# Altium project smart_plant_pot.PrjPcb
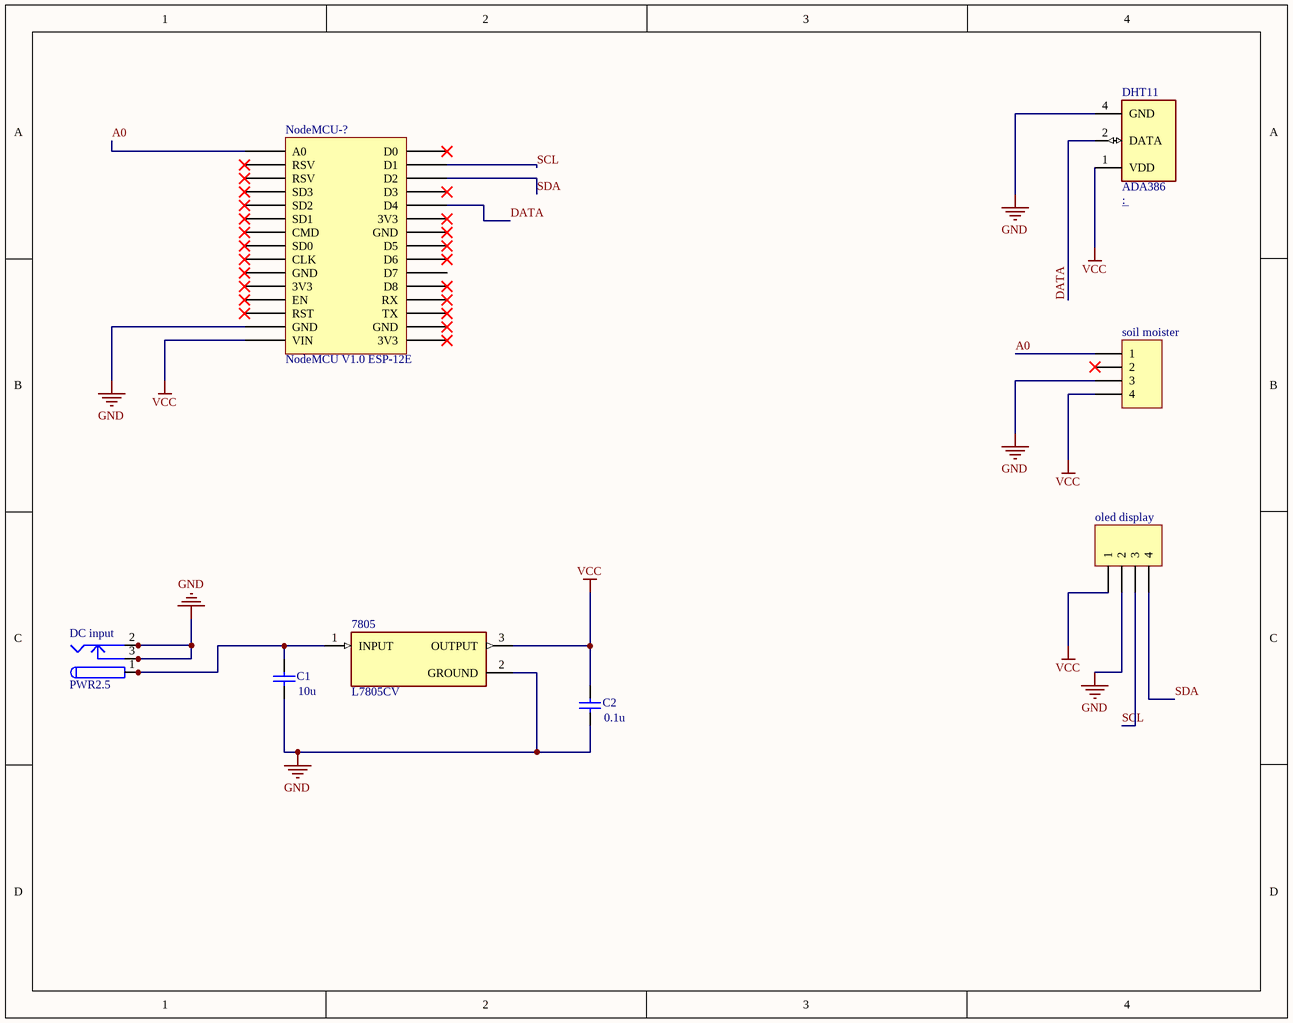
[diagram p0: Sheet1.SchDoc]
1 sheet, 8 parts. Net scope: global (net labels, ports and power ports of the same name join across sheets).
Board file: PCB1.PcbDoc

## Sheet Sheet1.SchDoc
size A; SheetNumber: 1; SheetTotal: 1

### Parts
7805  L7805CV  [TO255P1040X460X1968-3]
C1  value 10u  [C1206]
C2  value 0.1u  [C1206]
DC_input  PWR2.5  [KLD-0202]
DHT11  ADA386  [XDCR_ADA386]
NodeMCU-?  NodeMCU V1.0 ESP-12E  [NodeMCU V1.0 ESP-12E]
oled_display  (no value)  [HDR1X4]
soil_moister  (no value)  [HDR1X4]

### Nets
GND: 7805.2(GROUND) C1.1 C2.1 DC_input.2 DC_input.2A DC_input.2B DC_input.3 DC_input.3A DC_input.3B DHT11.4(GND) NodeMCU-?.GND oled_display.2 soil_moister.3
VCC: 7805.3(OUTPUT) C2.2 DHT11.1(VDD) NodeMCU-?.VIN oled_display.1 soil_moister.4
A0: NodeMCU-?.A0 soil_moister.1
DATA: DHT11.2(DATA) NodeMCU-?.D4
SCL: NodeMCU-?.D1 oled_display.3
SDA: NodeMCU-?.D2 oled_display.4
Net7805_1: 7805.1(INPUT) C1.2 DC_input.1 DC_input.1A DC_input.1B

Not connected (* = marked no-connect by the designer): NodeMCU-? 3V3* CLK* CMD* D0* D3* D5* D6* D7 D8* EN* RST* RSV* RX* SD0* SD1* SD2* SD3* TX*; soil_moister 2*

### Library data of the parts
7805 = L7805CV: Linear Voltage Regulator IC 1 Output 1.5A TO-220AB; MF: STMicroelectronics
C1 C2 = Cap Semi: Capacitor (Semiconductor SIM Model)
DC_input = PWR2.5: Low Voltage Power Supply Connector
DHT11 = ADA386: MF: Adafruit Industries
NodeMCU-? = NodeMCU V1.0 ESP-12E: NodeMCU V1.0 ESP8266 (ESP-12E)
oled_display = Header 4
soil_moister = Header 4: soil moister pin header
